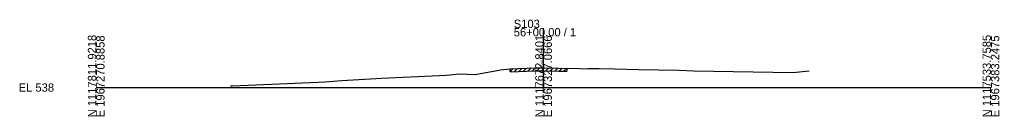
# Model space of a CAD drawing. Extents: x 974 to 1303, y 990 to 14518.
# Drawn here: x 974.3 to 1302.8, y 3990.3 to 4022.8 of the extents above; entities that cross this region are included whole.
import ezdxf

# ---------------------------------------------------------------- set-up
doc = ezdxf.new("R2010")
doc.units = 0
for name, color, linetype in [('Level 10', 7, 'Continuous'), ('Level 60', 7, 'Continuous'), ('Level 61', 7, 'Continuous'), ('Level 63', 7, 'Continuous')]:
    doc.layers.add(name, color=color, linetype=linetype)

msp = doc.modelspace()

# ---------------------------------------------------------------- linework, layer by layer
at = {"layer": 'Level 60'}
for p, q in [((1127.05, 4004.37), (1134.99, 4005.83)), ((1134.99, 4005.83), (1135.42, 4005.94)), ((1135.42, 4005.94), (1138.75, 4006.31)), ((1138.75, 4006.31), (1147.16, 4006.65)), ((1147.16, 4006.65), (1147.5, 4006.66)), ((1147.5, 4006.66), (1148.31, 4006.62)), ((1148.31, 4006.62), (1150, 4006.59)), ((1150, 4006.59), (1155.14, 4006.51)), ((1155.14, 4006.51), (1162.08, 4006.38)), ((1162.08, 4006.38), (1164.53, 4006.33)), ((1164.53, 4006.33), (1165.01, 4006.34)), ((1165.01, 4006.34), (1168.64, 4006.36)), ((1168.64, 4006.36), (1173.86, 4006.33)), ((1173.86, 4006.33), (1181.86, 4006.1)), ((1181.86, 4006.1), (1195.49, 4005.81)), ((1195.49, 4005.81), (1200.26, 4005.64)), ((1200.26, 4005.64), (1233.6, 4005)), ((1233.6, 4005), (1239.01, 4005.56)), ((1045.73, 4000.56), (1074.37, 4001.85)), ((1074.37, 4001.85), (1076.78, 4001.95)), ((1076.78, 4001.95), (1082.38, 4002.34)), ((1082.38, 4002.34), (1095.61, 4003.11)), ((1095.61, 4003.11), (1117.45, 4004.14)), ((1117.45, 4004.14), (1120.69, 4004.49)), ((1120.69, 4004.49), (1121.92, 4004.62)), ((1121.92, 4004.62), (1127.05, 4004.37)), ((1045.06, 4000.54), (1045.73, 4000.56))]:
    msp.add_line(p, q, dxfattribs=at)
at = {"layer": 'Level 61'}
for p, q in [((1138.75, 4005.31), (1139.79, 4006.35)), ((1138.75, 4005.31), (1138.75, 4006.31)), ((1138.75, 4005.31), (1147.16, 4005.65)), ((1140.25, 4005.37), (1141.29, 4006.41)), ((1141.75, 4005.43), (1142.79, 4006.47)), ((1143.25, 4005.49), (1144.29, 4006.53)), ((1144.75, 4005.55), (1145.79, 4006.59)), ((1146.25, 4005.61), (1147.29, 4006.65)), ((1147.16, 4005.65), (1147.5, 4005.66)), ((1147.5, 4005.66), (1148.31, 4005.62)), ((1147.75, 4005.64), (1148.72, 4006.61)), ((1148.31, 4005.62), (1150, 4005.59)), ((1149.25, 4005.61), (1150.23, 4006.59)), ((1150, 4005.59), (1155.14, 4005.51)), ((1150.75, 4005.58), (1151.73, 4006.57)), ((1152.25, 4005.56), (1153.23, 4006.54)), ((1153.75, 4005.53), (1154.73, 4006.52)), ((1155.14, 4005.51), (1157.79, 4005.46)), ((1155.25, 4005.51), (1156.23, 4006.49)), ((1156.75, 4005.48), (1157.73, 4006.46)), ((1157.79, 4006.46), (1157.79, 4005.46))]:
    msp.add_line(p, q, dxfattribs=at)
at = {"layer": 'Level 63'}
for p, q in [((1150, 4000), (1150, 4019.97)), ((1000, 4000), (1150, 4000)), ((1150, 4000), (1300, 4000))]:
    msp.add_line(p, q, dxfattribs=at)

# ---------------------------------------------------------------- texts
at = {"layer": 'Level 10'}
msp.add_text('544.59', height=0.9, rotation=90, dxfattribs=at).set_placement((1149.95, 4007.09))
at = {"layer": 'Level 63'}
for s, p in [('S103', (1140, 4019.97)), ('56+00.00 / 1', (1140, 4017.17)), ('EL 538', (974, 3998.6))]:
    msp.add_text(s, height=2.8, dxfattribs=at).set_placement(p)
for s, p in [('N 1117811.9218', (1000, 3990)), ('E 1967270.8858', (1002.8, 3990)), ('N 1117672.8401', (1150, 3990)), ('E 1967327.0666', (1152.8, 3990)), ('N 1117533.7585', (1300, 3990)), ('E 1967383.2475', (1302.8, 3990))]:
    msp.add_text(s, height=2.8, rotation=90, dxfattribs=at).set_placement(p)

doc.saveas('drawing.dxf')
